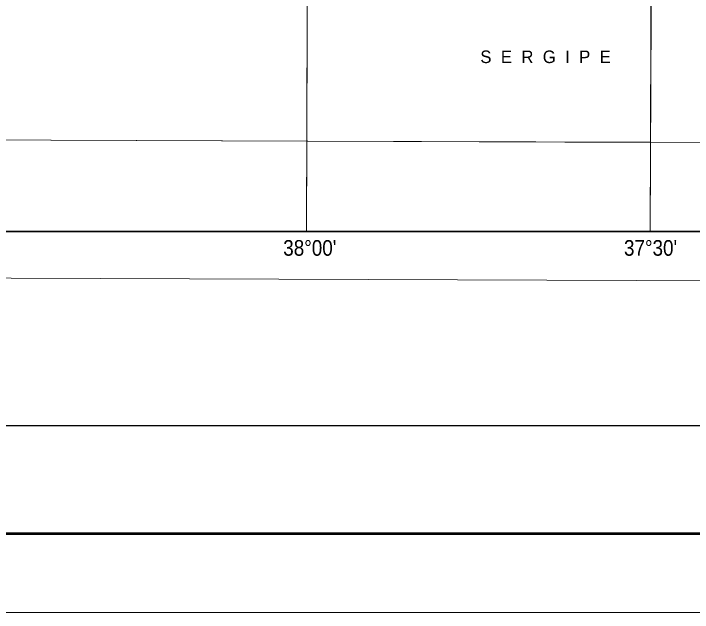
# Model space of a CAD drawing. Extents: x 553962 to 842807, y 8883888 to 9032388.
# Drawn here: x 576237 to 597882, y 8883888 to 8902976 of the extents above; entities that cross this region are included whole.
import ezdxf
from ezdxf.enums import TextEntityAlignment as Align

# ---------------------------------------------------------------- set-up
doc = ezdxf.new("R2010")
doc.units = 0
doc.header["$LTSCALE"] = 200
for name, color, linetype, lineweight in [('1', 7, 'Continuous', 13), ('3', 7, 'Continuous', 13), ('6', 7, 'Continuous', 13)]:
    doc.layers.add(name, color=color, linetype=linetype, lineweight=lineweight)

msp = doc.modelspace()

# ---------------------------------------------------------------- linework, layer by layer
at = {"layer": '1'}
msp.add_lwpolyline([(564751.7, 8894587.5), (664411.9, 8894209.9), (791388.5, 8893536.2)], dxfattribs=at)
at = {"layer": '3'}
msp.add_lwpolyline([(842807.3, 9032387.8), (842807.3, 8883887.8), (553961.7, 8883887.8), (553961.7, 9032387.8)], close=True, dxfattribs=at)
at = {"layer": '3', "lineweight": 53}
msp.add_lwpolyline([(840307.3, 9029887.8), (840307.3, 8886387.8), (560211.7, 8886387.8), (560211.7, 9029887.8)], close=True, dxfattribs=at)
at = {"layer": '3', "lineweight": 25}
msp.add_lwpolyline([(563033.9, 9026438.8), (793061.1, 9026438.8), (793495.6, 8889836.8), (563468.3, 8889836.8)], close=True, dxfattribs=at)
at = {"layer": '6', "lineweight": 35}
msp.add_lwpolyline([(574695.3, 8924769.6), (626625.7, 8924769.6), (626625.7, 8896026.7), (574695.3, 8896026.7)], close=True, dxfattribs=at)
at = {"layer": '6'}
for points in [[(585656.3, 8924738.8), (585614.8, 8909969.8), (585573.6, 8896026.7)], [(596655.5, 8924715.8), (596593.3, 8909930.3), (596531.7, 8896026.7)], [(574695.3, 8898953.2), (596544.3, 8898870.4), (626625.7, 8898710.8)]]:
    msp.add_lwpolyline(points, dxfattribs=at)
for points in [[(596575.8, 8909932.4), (585614.8, 8909969.8), (585583.8, 8898914.4), (596544.8, 8898874.9)], [(585583.8, 8898914.4), (574695.3, 8898953.2), (574695.3, 8896026.7), (585573.6, 8896026.7)], [(596544.3, 8898870.4), (596531.7, 8896026.7), (607492.3, 8896026.7), (607543.3, 8898835.3)]]:
    msp.add_lwpolyline(points, close=True, dxfattribs=at)

# ---------------------------------------------------------------- texts
msp.add_text('S  E  R  G  I  P  E', height=400, dxfattribs=at).set_placement((591118.1, 8901398.7))
at = {"layer": '6', "width": 0.9}
for s, p in [("38°00'", (585681.9, 8895256.8)), ("37°30'", (596546.8, 8895256.8))]:
    msp.add_text(s, height=500, dxfattribs=at).set_placement(p, align=Align.CENTER)

doc.saveas('drawing.dxf')
